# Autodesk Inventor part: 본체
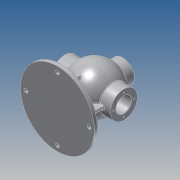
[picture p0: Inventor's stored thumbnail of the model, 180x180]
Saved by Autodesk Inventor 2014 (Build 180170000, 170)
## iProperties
Created: 2020-08
Part Number: 본체
Material: 알루미늄 6061
Document SubType Name: Modeling
Designer: kb542-17
Density: 2.71 g/cm^3
Appearance: 알루미늄 - 평지
Mass: 1759.18 g
Surface Area: 1342.51 cm^2
Volume: 649.144 cm^3
Author: kb542-17
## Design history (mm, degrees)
sketch "스케치1"
  geometry: L1 (-53, 0)-(53, 0); A1 r 53 centre (0, 0) between (53, 0) and (-53, 0); 1 further point
  constraints: 2 end point, 2 point on circle, 1 centre point, 1 coincident, 1 horizontal, 1 midpoint
  dimensions: "d6" = 53 radius of A1
revolve "회전1" sketch "스케치1" stored, may be unused: angle "d1" = 90 deg
sketch "스케치2"
  geometry: L1 (-43, 0)-(43, 0); A1 r 43 centre (0, 0) between (43, 0) and (-43, 0); 1 further point
  constraints: 2 end point, 2 point on circle, 1 centre point, 1 coincident, 1 horizontal, 1 midpoint
  dimensions: "d7" = 43 radius of A1
revolve "회전2" sketch "스케치2" stored, may be unused: angle "d3" = 90 deg
node "작업 평면2"
sketch "스케치6"
  geometry: C1 r 31 at (0, 0); 1 further point
  constraints: 1 centre point, 1 coincident
  dimensions: "d9" = 62 diameter of C1
extrude "돌출1" join sketch "스케치6" stored distance "d10" = 10; taper "d11" = 0 deg
sketch "스케치7"
  geometry: C1 r 31 at (0, 0) reference; 1 further point
  constraints: 1 vertical alignment
  dimensions: "d12" = 24 distance of point (0, 24) C1.centre
hole "구멍1" sketch "스케치7" at (0, 24) diameter "d13" = 3.242; stored, may be unused: countersink angle "d17" = 90 deg, drill point angle "d19" = 118 deg; dims "d14" = 12, "d15" = 4, "d16" = 2, "d18" = 15
sketch "스케치9"
  geometry: C1 r 31 at (0, 0) reference; C2 r 17.5 at (0, 0)
  constraints: 1 centre point, 1 coincident
  dimensions: "d23" = 35 diameter of C2
extrude "돌출2" cut sketch "스케치9" stored distance "d24" = 10; taper "d25" = 0 deg
node "작업 평면3"
sketch "스케치10"
  geometry: C1 r 27 at (0, 0); 1 further point
  constraints: 1 centre point, 1 coincident
  dimensions: "d27" = 54 diameter of C1
extrude "돌출3" join sketch "스케치10" stored distance "d28" = 10; taper "d29" = 0 deg
sketch "스케치11"
  geometry: C1 r 27 at (0, 0) reference; 1 further point
  constraints: 1 vertical alignment
  dimensions: "d30" = 20 distance of point (0, 20) C1.centre
hole "구멍2" sketch "스케치11" at (0, 20) diameter "d31" = 3.242; stored, may be unused: countersink angle "d35" = 90 deg, drill point angle "d37" = 118 deg; dims "d32" = 12, "d33" = 4, "d34" = 2, "d36" = 15
sketch "스케치12"
  geometry: C1 r 27 at (0, 0) reference; C2 r 13 at (0, 0)
  constraints: 1 centre point, 1 coincident
  dimensions: "d41" = 26 diameter of C2
extrude "돌출4" cut sketch "스케치12" stored distance "d42" = 10; taper "d43" = 0 deg
node "작업 평면4"
sketch "스케치14"
  geometry: C1 r 18.5 at (0, 0); C2 r 17.5 at (0, 0) reference; 1 further point
  constraints: 1 centre point, 1 coincident
  dimensions: "d45" = 37 diameter of C1
extrude "돌출5" cut sketch "스케치14" distance "d46" = 1.75; taper "d47" = 0 deg
node "작업 평면5"
sketch "스케치16"
  geometry: C1 r 85 at (0, 0); 1 further point
  constraints: 1 centre point, 1 coincident
  dimensions: "d49" = 170 diameter of C1
extrude "돌출6" join sketch "스케치16" distance "d50" = 10; taper "d51" = 0 deg
sketch "스케치17"
  geometry: C1 r 85 at (0, 0) reference; A1 r 72.5 centre (0, 0) between (0, 72.5) and (72.5, 0); 2 further points
  constraints: 4 point on circle, 2 horizontal alignment, 2 vertical alignment, 1 centre point, 1 coincident
  dimensions: "d52" = 145 diameter of A1
hole "구멍3" sketch "스케치17" at (0, 72.5), (72.5, 0), (0, -72.5), (-72.5, 0) diameter "d53" = 9; stored, may be unused: countersink angle "d57" = 90 deg, drill point angle "d59" = 118 deg; dims "d54" = 12, "d55" = 4, "d56" = 2, "d58" = 15
sketch "스케치18"
  geometry: L1 (-52, 4)-(52, 4); L2 (52, 4)-(52, -4); L3 (52, -4)-(-52, -4); L4 (-52, -4)-(-52, 4); C1 r 85 at (0, 0) reference; 2 further points
  constraints: 8 end point, 2 midpoint, 2 parallel, 1 horizontal, 1 horizontal alignment, 1 perpendicular, 1 vertical alignment
  dimensions: "d60" = 104 distance of L2.end L3.end; "d61" = 8 distance of L1.end L2.end
extrude "돌출7" join sketch "스케치18" stored distance "d62" = 10; taper "d63" = 0 deg
sketch "스케치19"
  geometry: L1 (-4, -43)-(4, -43); L2 (4, -43)-(4, 43); L3 (4, 43)-(-4, 43); L4 (-4, 43)-(-4, -43); L5 (-4, -43)-(4, 43); L6 (4, -43)-(-4, 43); C1 r 85 at (0, 0) reference
  constraints: 12 end point, 2 midpoint, 2 parallel, 1 horizontal, 1 perpendicular
  dimensions: "d64" = 8 distance of L2.end L3.end; "d65" = 86 distance of L1.end L2.end
extrude "돌출8" join sketch "스케치19" stored distance "d66" = 10; taper "d67" = 0 deg
chamfer "모따기1" distance "d73" = 1; stored, may be unused: second distance "d74" = 2, angle "d75" = 45 deg
fillet "모깎기1" dims "d76" = 3
fillet "모깎기2" dims "d77" = 3
node "작업 평면7"
sketch "스케치22"
  geometry: L1 (-27, 65)-(-27, 47.286) reference; L2 (-27, 65)-(27, 65) reference; 2 further points
  constraints: 1 other
  dimensions: "d79" = 9 distance from line of L2 point (0, 56); "d80" = 27 distance from line of L1 point (0, 56)
feature "엠보싱2" sketch "스케치22" dims "d6" = 53, "d18" = 15, "d81" = 0.5, "d82" = 0
node "솔리드1"
pattern_circular "원형 패턴1" dims angle "d21" = 360 deg
mirror "대칭1"
pattern_circular "원형 패턴2" dims angle "d39" = 360 deg
other parameters: "d8" = 68, "d26" = 65, "d44" = -16, "d48" = -85, "d78" = -71.5
